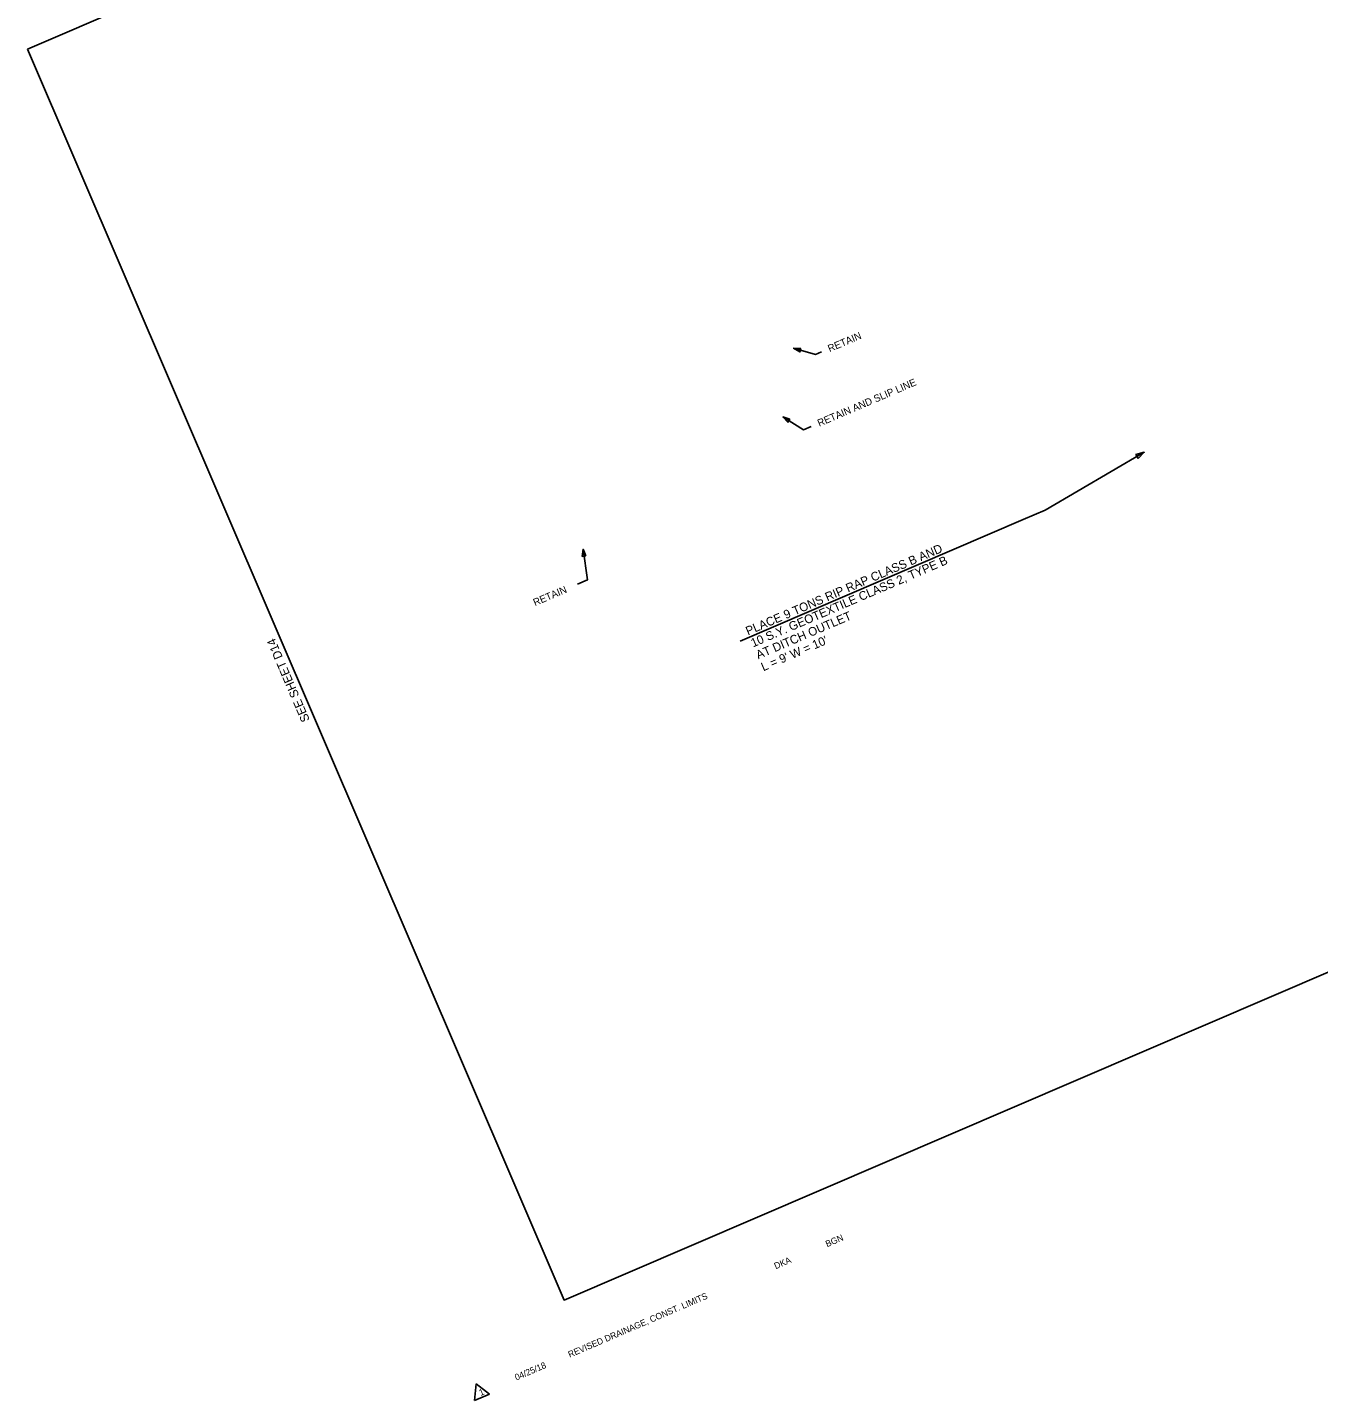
# Model space of a CAD drawing. Extents: x 1618261 to 1620114, y 1101131 to 1103031.
# Drawn here: x 1618328 to 1619221, y 1101131 to 1102081 of the extents above; entities that cross this region are included whole.
import ezdxf

# ---------------------------------------------------------------- set-up
doc = ezdxf.new("R2010")
doc.units = 0
for name, color, linetype in [('Level 2', 7, 'Continuous'), ('RD_EX_RW_TX', 7, 'Continuous'), ('RD_HC_Data_Tic', 7, 'Continuous'), ('RFP', 7, 'Continuous')]:
    doc.layers.add(name, color=color, linetype=linetype)

msp = doc.modelspace()

# ---------------------------------------------------------------- linework, layer by layer
at = {"layer": 'Level 2'}
msp.add_line((1619016.59, 1101740.71), (1618820.74, 1101656.66), dxfattribs=at)
for points in [[(1618877.03, 1101856.78), (1618872.86, 1101854.99), (1618857.69, 1101859.21)], [(1618869.87, 1101805.24), (1618864.45, 1101802.91), (1618850.28, 1101811.75)], [(1619016.59, 1101740.71), (1619031.74, 1101747.22), (1619100.3, 1101787.28)], [(1618708.08, 1101696.16), (1618715.08, 1101699.16), (1618711.99, 1101720.23)]]:
    msp.add_lwpolyline(points, dxfattribs=at)
for points in [[(1618862.69, 1101859.16), (1618857.69, 1101859.21), (1618862, 1101856.67)], [(1618855.06, 1101810.29), (1618850.28, 1101811.75), (1618853.69, 1101808.1)], [(1619096.08, 1101783.02), (1619100.3, 1101787.28), (1619094.52, 1101785.7)], [(1618713.97, 1101715.64), (1618711.99, 1101720.23), (1618711.41, 1101715.26)]]:
    msp.add_lwpolyline(points, close=True, dxfattribs=at)
at = {"layer": 'RD_EX_RW_TX'}
for p, q in [((1618638.08, 1101143.02), (1618636.85, 1101131.45)), ((1618647.31, 1101135.94), (1618638.08, 1101143.02)), ((1618636.85, 1101131.45), (1618647.31, 1101135.94))]:
    msp.add_line(p, q, dxfattribs=at)
at = {"layer": 'RFP'}
msp.add_lwpolyline([(1618327.62, 1102066.11), (1619552.64, 1102591.88), (1619565.97, 1102561.62), (1619719.68, 1102625.9), (1620077.33, 1101792.57), (1618698.92, 1101200.97)], close=True, dxfattribs=at)
msp.add_lwpolyline([(1618327.62, 1102066.11), (1619552.64, 1102591.88), (1619565.97, 1102561.62), (1619719.68, 1102625.9), (1620077.33, 1101792.57), (1618698.92, 1101200.97)], close=True, dxfattribs=at)
msp.add_lwpolyline([(1618327.62, 1102066.11), (1619552.64, 1102591.88), (1619565.97, 1102561.62), (1619719.68, 1102625.9), (1620077.33, 1101792.57), (1618698.92, 1101200.97)], close=True, dxfattribs=at)
msp.add_lwpolyline([(1618327.62, 1102066.11), (1619552.64, 1102591.88), (1619565.97, 1102561.62), (1619719.68, 1102625.9), (1620077.33, 1101792.57), (1618698.92, 1101200.97)], close=True, dxfattribs=at)
msp.add_lwpolyline([(1618327.62, 1102066.11), (1619552.64, 1102591.88), (1619565.97, 1102561.62), (1619719.68, 1102625.9), (1620077.33, 1101792.57), (1618698.92, 1101200.97)], close=True, dxfattribs=at)

# ---------------------------------------------------------------- texts
at = {"layer": 'Level 2'}
for s, height, rotation, p in [('RETAIN', 5, 23.22835, (1618882.61, 1101856.46)), ('RETAIN AND SLIP LINE', 5, 23.22835, (1618875.45, 1101804.92)), ('PLACE 9 TONS RIP RAP CLASS B AND', 6, 23.22835, (1618826.08, 1101660.58)), ('10 S.Y. GEOTEXTILE CLASS 2, TYPE B', 6, 23.22835, (1618829.63, 1101652.31)), ('RETAIN', 5, 23.22319, (1618678.78, 1101680.87)), ('AT DITCH OUTLET', 6, 23.22835, (1618833.18, 1101644.04)), ("L = 9' W = 10'", 6, 23.22835, (1618836.73, 1101635.77))]:
    msp.add_text(s, height=height, rotation=rotation, dxfattribs=at).set_placement(p)
at = {"layer": 'RD_EX_RW_TX'}
for s, p in [('BGN', (1618880.86, 1101237.47)), ('DKA', (1618845.32, 1101222.21)), ('REVISED DRAINAGE, CONST. LIMITS', (1618702.77, 1101161.03)), ('04/25/18', (1618665.86, 1101145.19)), ('1', (1618641.13, 1101134.57))]:
    msp.add_text(s, height=4.4, rotation=23.22998, dxfattribs=at).set_placement(p)
at = {"layer": 'RD_HC_Data_Tic'}
msp.add_text('SEE SHEET D14', height=6, rotation=113.22835, dxfattribs=at).set_placement((1618523.04, 1101602.22))

doc.saveas('drawing.dxf')
